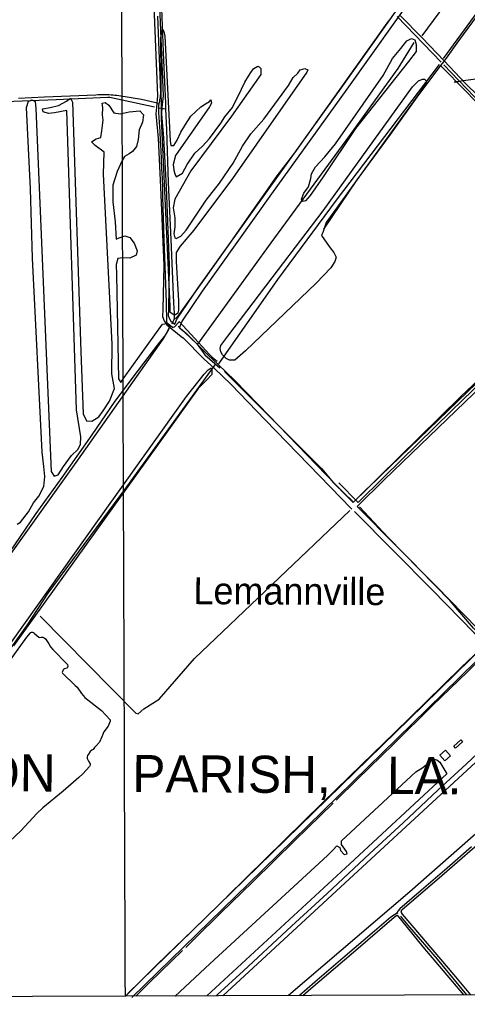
# Model space of a CAD drawing. Extents: x 3392644 to 3430565, y 576657 to 602123.
# Drawn here: x 3406749 to 3409164, y 582044 to 587349 of the extents above; entities that cross this region are included whole.
import ezdxf

# ---------------------------------------------------------------- set-up
doc = ezdxf.new("R2010")
doc.units = 0
for name, color, linetype in [('V-BLDG-OTLN', 7, 'Continuous'), ('V-DTCH-CNTR', 7, 'Continuous'), ('V-GRID-FRAM', 7, 'Continuous'), ('V-GRID-MAJR', 7, 'Continuous'), ('V-ROAD-CNTR', 7, 'Continuous'), ('V-SITE-VEGE', 7, 'Continuous'), ('V-TOPO-GNAM-IDEN', 7, 'Continuous'), ('V-TOPO-SHOR', 7, 'Continuous'), ('V-UTIL-LINE', 7, 'Continuous')]:
    doc.layers.add(name, color=color, linetype=linetype)

msp = doc.modelspace()

# ---------------------------------------------------------------- linework, layer by layer
at = {"layer": 'V-BLDG-OTLN'}
for points in [[(3409137.6, 583454.6), (3409100.6, 583421), (3409091.2, 583431.3), (3409128.2, 583464.9)], [(3409042.7, 583352.1), (3409072.2, 583379.1), (3409045.2, 583408.7), (3409015.7, 583381.7)]]:
    msp.add_lwpolyline(points, close=True, dxfattribs=at)
at = {"layer": 'V-DTCH-CNTR'}
for points in [[(3409647, 587959), (3409624.9, 587929.9), (3409540.6, 587814.5), (3409446.6, 587687.7), (3409353.5, 587558.7), (3409216, 587370.3), (3409116.2, 587234.7), (3409048.9, 587141.1), (3409039.4, 587126.6), (3409035.3, 587120.4), (3409019.6, 587101.1), (3409014.3, 587094.6), (3408890.9, 586930.1), (3408748, 586728.7), (3408567.8, 586484.8), (3408387.6, 586219.2)], [(3407492.4, 587367.2), (3407508.1, 586956.3), (3407507.8, 586948.1), (3407507.1, 586940), (3407506.3, 586931.8), (3407505.2, 586923.7), (3407503.8, 586915.6), (3407502.2, 586907.6), (3407500.4, 586899.7), (3407500, 586897.4), (3407499.3, 586893.7), (3407498.4, 586887.8), (3407497.7, 586881.8), (3407497.3, 586875.8), (3407497, 586869.7), (3407497, 586863.7), (3407497.2, 586857.7), (3407497.6, 586851.7), (3407498.2, 586845.7), (3407501.5, 586795.5), (3407504.6, 586745.4), (3407507.5, 586695.2), (3407510.1, 586645), (3407512.5, 586594.8), (3407514.7, 586544.6), (3407516.7, 586494.4), (3407518.5, 586444.2), (3407520.1, 586394), (3407527.2, 586164.2)], [(3409039.4, 587126.6), (3408919.7, 587250.4), (3408803.6, 587369)], [(3409928.4, 586167.2), (3409775.2, 586325.2), (3409562, 586545.6), (3409327.7, 586783.7), (3409156.4, 586961.6), (3409019.6, 587101.1)], [(3409039.4, 587126.6), (3409153.9, 587005.2), (3409288.2, 586873), (3409454.9, 586698.5), (3409643, 586502.2), (3409785.6, 586360.5), (3409964.8, 586171.9)], [(3407500, 586897.4), (3407405.1, 586917.7), (3407282.9, 586937.4), (3407272.8, 586938.9), (3407262.6, 586940.2), (3407252.3, 586941.3), (3407242.1, 586942.2), (3407231.8, 586943), (3407221.5, 586943.4), (3407211.2, 586943.7), (3407201, 586943.8), (3407190.7, 586943.6), (3407180.4, 586943.3), (3407170.1, 586942.7), (3407159.8, 586941.9), (3407020.9, 586935.8), (3406881.9, 586930), (3406742.9, 586924.3)], [(3407527.2, 586164.2), (3407539.5, 585825.5), (3407541.7, 585715.3), (3407545.1, 585713), (3407574.1, 585689.7), (3407576.4, 585689.6), (3407583.3, 585691.8), (3407608.8, 585719.6), (3407610, 585721.9), (3407713.3, 585608.4), (3407772.1, 585543.6), (3407788.8, 585526.3), (3407813.4, 585506.4)], [(3410023.7, 586158.2), (3410001, 586135), (3409981, 586115.2), (3409793.5, 585934.6), (3409482.4, 585632), (3409077.8, 585238.5), (3408713.3, 584882), (3408575.6, 584745.8), (3408572.1, 584747.2), (3408471.1, 584851.2)], [(3409182.8, 582089.4), (3409092.7, 582198.3), (3408907.2, 582416.2), (3408813.8, 582525.5), (3408808.5, 582534.5), (3408807.9, 582537.3), (3408807.3, 582543.5), (3408808.1, 582544.9), (3408809.5, 582548.3), (3409025.3, 582733.7), (3409286, 582959.6), (3409402.1, 583061.5), (3409500.5, 583147.9), (3409737.2, 583347.4), (3409967.1, 583549.1), (3410164.7, 583718.4), (3410319.6, 583853.5), (3410527.7, 584033), (3410699.4, 584182.2), (3410804.5, 584272.9)], [(3408276.7, 582086.1), (3408319.8, 582123.9), (3408549, 582320.8), (3408768.3, 582508.3), (3408782.9, 582519.7), (3408784.3, 582519), (3408923.9, 582348.8), (3409143.1, 582089.3)]]:
    msp.add_lwpolyline(points, dxfattribs=at)
at = {"layer": 'V-GRID-FRAM'}
msp.add_lwpolyline([(3396720.3, 600227.7), (3428325.7, 600342.6), (3428399.7, 582159.3), (3396778.5, 582044.3), (3396720.3, 600227.7)], dxfattribs=at)
at = {"layer": 'V-GRID-MAJR'}
msp.add_spline([(3407318.9, 582082.7), (3407297.7, 588140.7), (3407276.6, 594201.8), (3407255.4, 600262.9), (3407255.4, 600266)], degree=3, dxfattribs=at)
at = {"layer": 'V-ROAD-CNTR'}
for points in [[(3407363.9, 589730.8), (3407387.6, 589307.2), (3407422.5, 588520.5), (3407454.4, 587862.2), (3407492.5, 586938.6), (3407486.2, 586877), (3407483.2, 586840.9), (3407495.3, 586709.7), (3407509.1, 586445.7), (3407525.9, 586023.7), (3407521.7, 585787.5), (3407518.7, 585747.8), (3407528.4, 585724.8), (3407542.5, 585702.5), (3407629.7, 585633.1)], [(3407393.4, 589740.1), (3407417.6, 589308.7), (3407452.4, 588521.9), (3407484.4, 587863.5), (3407522.6, 586937.7), (3407516, 586874.2), (3407513.3, 586841), (3407525.2, 586711.9), (3407539.1, 586447), (3407555.9, 586024.1), (3407551.7, 585786.1), (3407549.2, 585752.7), (3407555.1, 585738.8), (3407565.1, 585722.8), (3407586.1, 585706.1)], [(3407586.1, 585706.1), (3407597.1, 585734.1), (3407711.2, 585901.9), (3408084.8, 586426.5), (3408491.3, 586992), (3408869.5, 587524.3), (3409161.2, 587932.8), (3409275.8, 588090.6), (3409321.6, 588159.8)], [(3407610.7, 585686.6), (3407623.8, 585720), (3407735.8, 585884.8), (3408109.2, 586409), (3408515.7, 586974.6), (3408894, 587506.9), (3409185.5, 587915.3), (3409300.4, 588073.5), (3409345.2, 588141.1)], [(3409939, 586099.5), (3409831.9, 585994.6), (3409369.7, 585539.7), (3408696.3, 584891.4), (3408548.3, 584744.8)], [(3409949.3, 586067.6), (3409852.9, 585973.2), (3409390.7, 585518.2), (3408717.3, 584869.9), (3408569.4, 584723.5)], [(3407610.7, 585686.6), (3407648.3, 585656.6)], [(3407649.7, 585655.4), (3407764.8, 585538.8), (3407818, 585491.6), (3407910.3, 585402.9), (3408095, 585212.5), (3408504.6, 584788.8), (3408548.3, 584744.8)], [(3407628.3, 585634.3), (3407744.2, 585517.1), (3407797.6, 585469.6), (3407889.1, 585381.6), (3408073.5, 585191.6), (3408483.2, 584767.8), (3408507.5, 584743.3)], [(3408508.9, 584741.9), (3408540.8, 584709.7)], [(3408554.2, 584696.2), (3408973.7, 584273.2), (3409199.9, 584041.6), (3409268.5, 583986.1)], [(3408569.4, 584723.5), (3408995.1, 584294.2), (3409220.1, 584063.8), (3409290, 584007.2)], [(3409268.5, 583986.1), (3408926.5, 583651.5), (3407961.3, 582711), (3407333, 582096.6)], [(3409301.6, 583976.6), (3408947.4, 583630), (3407982.3, 582689.5), (3407354, 582075.2)]]:
    msp.add_lwpolyline(points, dxfattribs=at)
at = {"layer": 'V-SITE-VEGE'}
for p, q in [((3407001.1, 586908.9), (3407022.2, 586924.6)), ((3407022.2, 586924.6), (3407033.7, 586903.6)), ((3406786.2, 586875.8), (3406795.6, 586908.3)), ((3406806.9, 586435.7), (3406786.2, 586875.8)), ((3406795.6, 586908.3), (3406816.4, 586915.7)), ((3406816.4, 586915.7), (3406832.5, 586906.9)), ((3406832.5, 586906.9), (3406835.2, 586869.9)), ((3406835.2, 586869.9), (3406919.2, 584912.5)), ((3406872.2, 586868.5), (3406913.5, 586875.2)), ((3406875.7, 586852), (3406872.2, 586868.5)), ((3406913.5, 586875.2), (3406959.1, 586885.8)), ((3406959.1, 586885.8), (3407001.1, 586908.9)), ((3407033.7, 586903.6), (3407078.7, 585559.5)), ((3407193.8, 586897.7), (3407210.3, 586901.2)), ((3407197, 586873), (3407193.8, 586897.7)), ((3407195.6, 586836.1), (3407197, 586873)), ((3407210.3, 586901.2), (3407230.4, 586888.2)), ((3407230.4, 586888.2), (3407257.6, 586846.1)), ((3406904.1, 586842.7), (3406875.7, 586852)), ((3406937.1, 586845.6), (3406904.1, 586842.7)), ((3407003.3, 586859.6), (3406937.1, 586845.6)), ((3407054.7, 585244.2), (3407003.3, 586859.6)), ((3407198.7, 586807.2), (3407195.6, 586836.1)), ((3407257.6, 586846.1), (3407290.3, 586840.8)), ((3407290.3, 586840.8), (3407340, 586851.3)), ((3407340, 586851.3), (3407397.7, 586857.4)), ((3407397.7, 586857.4), (3407417.5, 586836.1)), ((3407417.5, 586836.1), (3407411.9, 586795.3)), ((3407192.4, 586750), (3407198.7, 586807.2)), ((3407411.9, 586795.3), (3407394, 586754.9)), ((3407136.8, 586690.4), (3407162, 586705.9)), ((3407162, 586705.9), (3407187, 586713.2)), ((3407187, 586713.2), (3407192.4, 586750)), ((3407394, 586754.9), (3407387.9, 586701.7)), ((3407156.6, 586669.2), (3407136.8, 586690.4)), ((3407204.6, 586634.6), (3407156.6, 586669.2)), ((3407378.3, 586665.1), (3407356.8, 586637.2)), ((3407387.9, 586701.7), (3407378.3, 586665.1)), ((3407200.2, 586515.7), (3407204.6, 586634.6)), ((3407314.7, 586610), (3407301.6, 586589.9)), ((3407339.9, 586625.5), (3407314.7, 586610)), ((3407356.8, 586637.2), (3407339.9, 586625.5)), ((3407301.6, 586589.9), (3407274.7, 586529.3)), ((3407248.6, 585598.3), (3407200.2, 586515.7)), ((3407274.7, 586529.3), (3407251.5, 586456.3)), ((3407251.5, 586456.3), (3407252.2, 586366)), ((3406817.8, 586061.7), (3406806.9, 586435.7)), ((3407252.2, 586366), (3407264.7, 586258.7)), ((3407264.7, 586258.7), (3407269.5, 586164.1)), ((3407286.2, 586171.7), (3407315.3, 586183)), ((3407315.3, 586183), (3407343.8, 586173.7)), ((3407269.5, 586164.1), (3407286.2, 586171.7)), ((3407343.8, 586173.7), (3407367.3, 586144.1)), ((3407367.3, 586144.1), (3407382.2, 586102.5)), ((3407377.2, 586078.1), (3407343.8, 586062.9)), ((3407382.2, 586102.5), (3407377.2, 586078.1)), ((3406869.7, 585017), (3406817.8, 586061.7)), ((3407278, 586061.2), (3407268.6, 586028.7)), ((3407268.6, 586028.7), (3407270.6, 585971.1)), ((3407302.8, 586064.4), (3407278, 586061.2)), ((3407343.8, 586062.9), (3407302.8, 586064.4)), ((3407270.6, 585971.1), (3407282.8, 585412.3)), ((3407311.8, 585419.5), (3407519.7, 585707.4)), ((3407519.7, 585707.4), (3407544.5, 585710.6)), ((3407544.5, 585710.6), (3407556.2, 585693.7)), ((3407551.5, 585677.5), (3407520.8, 585625.3)), ((3407556.2, 585693.7), (3407551.5, 585677.5)), ((3407520.8, 585625.3), (3407061.2, 584973)), ((3407246.8, 585438.3), (3407248.6, 585598.3)), ((3407078.7, 585559.5), (3407090.9, 585222.3)), ((3407260.3, 585359.8), (3407246.8, 585438.3)), ((3407649.1, 585316.7), (3407743.9, 585436.4)), ((3407743.9, 585436.4), (3407765.4, 585460.2)), ((3407785, 585434.9), (3407759.3, 585407.1)), ((3407765.4, 585460.2), (3407782.2, 585471.9)), ((3407782.2, 585471.9), (3407785.9, 585459.5)), ((3407785.9, 585459.5), (3407785, 585434.9)), ((3407282.8, 585412.3), (3407294.4, 585391.4)), ((3407294.4, 585391.4), (3407311.8, 585419.5)), ((3407759.3, 585407.1), (3407712.3, 585359.5)), ((3407712.3, 585359.5), (3406716.1, 583971.7)), ((3407233.1, 585291), (3407260.3, 585359.8)), ((3407198.4, 585238.9), (3407233.1, 585291)), ((3407246.2, 584752.7), (3407649.1, 585316.7)), ((3407078.2, 585099.6), (3407054.7, 585244.2)), ((3407090.9, 585222.3), (3407110.1, 585184.7)), ((3407176.6, 585206.9), (3407198.4, 585238.9)), ((3407110.1, 585184.7), (3407138.8, 585183.6)), ((3407138.8, 585183.6), (3407176.6, 585206.9)), ((3407076.6, 585058.6), (3407078.2, 585099.6)), ((3406879.1, 584938.7), (3406869.7, 585017)), ((3407029.2, 584998.8), (3407063.3, 585030.4)), ((3407063.3, 585030.4), (3407076.6, 585058.6)), ((3407061.2, 584973), (3406567.3, 584285.1)), ((3406985.9, 584938.8), (3407029.2, 584998.8)), ((3406885.3, 584885.1), (3406879.1, 584938.7)), ((3406919.2, 584912.5), (3406934.7, 584887.3)), ((3406955.6, 584894.8), (3406985.9, 584938.8)), ((3406879.3, 584831.9), (3406885.3, 584885.1)), ((3406934.7, 584887.3), (3406955.6, 584894.8)), ((3406852.7, 584779.5), (3406879.3, 584831.9)), ((3406704.5, 583992.6), (3407246.2, 584752.7)), ((3406796.2, 584695.4), (3406822.6, 584743.7)), ((3406822.6, 584743.7), (3406852.7, 584779.5)), ((3406753, 584639.5), (3406796.2, 584695.4)), ((3406736.1, 584627.8), (3406753, 584639.5)), ((3407844.5, 582084.6), (3409233.2, 583365.6)), ((3408952.8, 583339), (3408978.3, 583362.7)), ((3408978.3, 583362.7), (3408998.7, 583357.9)), ((3408885.3, 583292.3), (3408923.1, 583315.5)), ((3408923.1, 583315.5), (3408952.8, 583339)), ((3408998.7, 583357.9), (3409014.6, 583345)), ((3409014.6, 583345), (3409053.4, 583282)), ((3408485.3, 582921.1), (3408885.3, 583292.3)), ((3409053.4, 583282), (3408530.1, 582796.3)), ((3409392.7, 583121.6), (3408853.2, 582644.8)), ((3408438.2, 582869.4), (3408459.7, 582893.3)), ((3408459.7, 582893.3), (3408475.8, 582884.5)), ((3408484.6, 582900.6), (3408485.3, 582921.1)), ((3408512, 582862.6), (3408484.6, 582900.6)), ((3407774.6, 582257.6), (3408408.5, 582841.8)), ((3408408.5, 582841.8), (3408438.2, 582869.4)), ((3408475.8, 582884.5), (3408479.3, 582867.9)), ((3408479.3, 582867.9), (3408499, 582846.7)), ((3408499, 582846.7), (3408515.6, 582850.2)), ((3408515.6, 582850.2), (3408512, 582862.6)), ((3408530.1, 582796.3), (3407758.9, 582084.3)), ((3408853.2, 582644.8), (3408199.1, 582085.9)), ((3407587.2, 582083.6), (3407774.6, 582257.6)), ((3407758.9, 582084.3), (3407587.2, 582083.6)), ((3408199.1, 582085.9), (3407844.5, 582084.6))]:
    msp.add_line(p, q, dxfattribs=at)
for points in [[(3407593.6, 586043.8), (3407606, 585832.1), (3407606, 585782.3), (3407601.9, 585765.6), (3407589.4, 585757.3), (3407581.1, 585757.3), (3407560.4, 585769.8), (3407560.4, 585803), (3407514.7, 586815.9), (3407510.6, 587251.8), (3407518.9, 587297.5), (3407527.2, 587285), (3407531.3, 587260.1), (3407560.4, 586695.5), (3407564.5, 586670.6), (3407581.1, 586670.6), (3407597.7, 586699.7), (3407618.4, 586741.2), (3407643.3, 586782.7), (3407672.4, 586828.4), (3407726.3, 586878.2), (3407751.2, 586894.8), (3407771.9, 586907.3), (3407780.2, 586915.6), (3407784.4, 586899), (3407771.9, 586878.2), (3407589.4, 586616.7), (3407577, 586566.9), (3407581.1, 586537.8), (3407585.3, 586517), (3407593.6, 586500.4), (3407626.7, 586521.2), (3407651.6, 586566.9), (3407693.1, 586629.1), (3407734.6, 586666.5), (3407771.9, 586708), (3407834.1, 586791), (3407854.9, 586824.2), (3407896.4, 586874.1), (3407946.1, 586973.7), (3407962.7, 587011), (3407983.5, 587044.3), (3408000.1, 587069.2), (3408012.5, 587085.8), (3408033.3, 587098.2), (3408041.6, 587094.1), (3408049.9, 587085.8), (3408049.9, 587052.6), (3407892.2, 586828.4), (3407672.4, 586533.6), (3407585.3, 586380), (3407577, 586334.4), (3407585.3, 586280.4), (3407585.3, 586230.6), (3407581.1, 586193.2), (3407585.3, 586172.5), (3407593.6, 586168.3), (3407618.4, 586180.8), (3407647.5, 586214), (3407755.3, 586375.9), (3407825.9, 586467.2), (3407900.5, 586575.2), (3407950.3, 586666.5), (3407995.9, 586732.9), (3408066.4, 586811.8), (3408145.3, 586919.7), (3408199.2, 586994.4), (3408224.1, 587036), (3408249, 587060.9), (3408261.4, 587077.5), (3408286.3, 587085.8), (3408302.9, 587077.5), (3408298.7, 587065), (3407896.4, 586492.1), (3407689, 586214), (3407614.3, 586126.8), (3407593.6, 586093.6)], [(3408560.1, 586762), (3408385.9, 586500.4), (3408315.3, 586400.8), (3408290.4, 586371.7), (3408278, 586367.6), (3408269.7, 586380), (3408282.2, 586413.3), (3408307, 586446.5), (3408319.5, 586492.1), (3408323.6, 586517), (3408344.4, 586554.4), (3408394.2, 586608.4), (3408452.2, 586678.9), (3408709.4, 587048.4), (3408759.2, 587139.7), (3408804.8, 587193.7), (3408838, 587235.2), (3408862.9, 587247.7), (3408879.5, 587239.4), (3408887.8, 587214.5), (3408887.8, 587177.1), (3408846.3, 587123.1)], [(3408145.3, 586002.3), (3408385.9, 586317.8), (3408867, 586986.1), (3408900.2, 587019.4), (3408921, 587027.7), (3408933.4, 587027.7), (3408941.7, 587019.4), (3408941.7, 587002.7), (3408800.7, 586807.6), (3408402.4, 586255.5), (3408385.9, 586205.7), (3408377.6, 586184.9), (3408406.6, 586143.4), (3408423.2, 586118.5), (3408443.9, 586093.6), (3408456.4, 586068.7), (3408448.1, 586043.8), (3408427.3, 586010.6), (3408348.5, 585927.5), (3407966.9, 585562.2), (3407908.8, 585512.4), (3407879.8, 585512.4), (3407863.2, 585520.7), (3407842.4, 585541.5), (3407834.1, 585558.1), (3407830, 585574.7), (3407834.1, 585591.3), (3407871.5, 585641.1)]]:
    msp.add_lwpolyline(points, close=True, dxfattribs=at)
at = {"layer": 'V-TOPO-SHOR'}
for p, q in [((3408919.9, 587261.6), (3409456.6, 587991.4)), ((3409035.7, 587139.6), (3409612.3, 587930.8)), ((3408785.1, 587365.1), (3409022, 587119.5)), ((3407501.6, 586873), (3407536.3, 586867.9)), ((3408788.2, 582529), (3408785.3, 582532.9))]:
    msp.add_line(p, q, dxfattribs=at)
for points in [[(3407464.2, 588446.3), (3407466.2, 588409.9), (3407478.1, 588196.5), (3407490.7, 587925.7), (3407491.1, 587917.4), (3407502.7, 587678.6), (3407513, 587408.8), (3407525.4, 587127.6), (3407535.2, 586898.2), (3407536.3, 586867.9), (3407540.5, 586754.7), (3407550.5, 586470.9), (3407565.1, 586162.9)], [(3408738.8, 587341.8), (3408541.8, 587067.1), (3408231, 586630.9), (3408130.4, 586498.9), (3408099.2, 586454.3), (3407959.5, 586255), (3407885.8, 586149.5)], [(3407709.8, 585598.2), (3408105.3, 586144.7), (3408529.4, 586724), (3408668, 586917.1), (3408790.4, 587085.6), (3408875.9, 587225.2)], [(3409011.6, 587106.9), (3408456.9, 586375.5), (3408138.8, 585948.1), (3407820.9, 585492.1)], [(3409036.2, 587104.6), (3409323.3, 586806.8), (3409588.6, 586539.2), (3409972.5, 586141.7)], [(3406624.4, 586906.3), (3406945.4, 586918.2), (3407221.8, 586931.5), (3407235.6, 586929.9), (3407476, 586878.5)], [(3407565.1, 586162.9), (3407579.4, 585821.2), (3407583, 585764), (3407582.6, 585744.1), (3407579.6, 585729.7), (3407571.6, 585712.7), (3407569.5, 585707.2)], [(3407885.8, 586149.5), (3407739.8, 585944), (3407600.1, 585748.7), (3407579.6, 585729.7)], [(3407556, 585687.5), (3407535.2, 585649.4), (3407498.5, 585602), (3407388.8, 585459), (3407262.2, 585291), (3407138, 585109.1), (3406977, 584879.8), (3406836.7, 584685.2), (3406694.1, 584477.6), (3406534.8, 584261.3), (3406427.1, 584115.6), (3406406.7, 584093.3), (3406403.8, 584087.2), (3406403.7, 584081), (3406406.3, 584074), (3406413, 584063.6), (3406476.1, 583990), (3406593.5, 583874), (3406611.7, 583856.5), (3406619.8, 583846.7), (3406623.8, 583843.1), (3406651.8, 583830.8), (3406657.9, 583828.7)], [(3407602.9, 585696.2), (3407705.7, 585598.2), (3407746.9, 585541), (3407829.1, 585471.6)], [(3407800.7, 585486.7), (3407528.4, 585109.8), (3407325, 584828.7), (3406901.6, 584256.7), (3406790.1, 584084.8), (3406691.7, 583949.2), (3406626.1, 583853.4)], [(3407853.8, 585451.2), (3408376.1, 584928.6), (3408442, 584851)], [(3408573.4, 584769.5), (3409128.7, 585316.6), (3409259.4, 585440)], [(3408545.4, 584750.7), (3408452.7, 584839.4), (3408442, 584851)], [(3406859.2, 584131.2), (3407375.6, 583608.8), (3407388.8, 583605.5), (3407418.3, 583632), (3407500.6, 583685.1), (3407691.1, 583903.4), (3408529.1, 584701.2)], [(3409260.4, 584008), (3409197.5, 584067.2), (3409071.7, 584215.1), (3408737.4, 584556.9), (3408581.8, 584721.2)], [(3406699.9, 583895.9), (3406788.3, 584019.1), (3406806.6, 584042.7), (3406808, 584044.1), (3406813.5, 584045.3), (3406817.7, 584045.2), (3406823.8, 584043.1), (3406827.2, 584040.2), (3406842, 584027.6), (3406851.4, 584018.4), (3406858.3, 584016.2), (3406865.2, 584018.2), (3406873.4, 584018.7), (3406880.9, 584015.8), (3406887.7, 584010.1), (3406895.7, 583999.7), (3406905.6, 583982.3), (3406914.9, 583966.3), (3406927.7, 583952.3), (3407004.3, 583873.8), (3407007, 583871.7), (3407008.8, 583860), (3407004.6, 583851.8), (3406997, 583850.6), (3406988.7, 583847.4), (3406983.8, 583842.7), (3406978, 583829), (3406980, 583824.2), (3407047.9, 583757.5), (3407059.4, 583748.4), (3407082.1, 583715), (3407100.2, 583694), (3407190.7, 583622.7), (3407236.4, 583572.4), (3407237.6, 583565.5), (3407225.4, 583538.9), (3407203.5, 583508.5), (3407191.2, 583480.6), (3407179.7, 583453.4), (3407159.3, 583431.8), (3407152.3, 583423), (3407145.2, 583413.5), (3407138.9, 583409.6), (3407129.9, 583402.2), (3407120, 583388.7), (3407115, 583380.5), (3407112.1, 583373), (3407113.3, 583364.8), (3407120.5, 583349.5), (3407128.5, 583335.6), (3407128.3, 583328.7), (3407125.4, 583321.9), (3407088.9, 583281.5), (3407067.2, 583262.7)], [(3409261.2, 583980.1), (3409132.1, 583857.6), (3408941.4, 583669.3), (3408771.1, 583503.2), (3408593.8, 583332.4), (3408383.6, 583128.1), (3408176.9, 582923.7), (3407971.6, 582722.1), (3407866.2, 582618.2)], [(3409301, 583966.6), (3409164.1, 583832.5), (3408976.5, 583649.9), (3408765.8, 583442.3), (3408569.8, 583251.6), (3408456, 583139.7)], [(3409711.5, 583850.7), (3409628.9, 583774.1), (3409533.7, 583685.4), (3409431.4, 583590), (3409313.2, 583481.9), (3409157, 583334.7), (3409005.8, 583196.4), (3408816.7, 583017.7), (3408638.2, 582853.1), (3408407.1, 582637.4), (3408215.9, 582460.1), (3407956.9, 582220.3), (3407814.1, 582089.4), (3407808.9, 582084.4)], [(3407067.2, 583262.7), (3406984, 583188.2), (3406874.3, 583098.5), (3406842.1, 583068.2), (3406755.7, 582975.2), (3406665.3, 582890.6)], [(3408439.1, 583122.8), (3408235.5, 582924), (3408005.8, 582700.3), (3407834.4, 582533.1), (3407693.9, 582394.3), (3407644.7, 582345.7)], [(3409186.4, 582887.6), (3409055.1, 582773.8), (3408915.6, 582654.6), (3408799.7, 582554.2), (3408789.1, 582541.4), (3408785.5, 582533.2), (3408785.3, 582532.9), (3408782.7, 582529.8), (3408771.6, 582521.8), (3408750.8, 582509.2), (3408662.1, 582433.6), (3408491.8, 582287), (3408341.7, 582157.8), (3408259.1, 582086.1)], [(3407827.1, 582578.7), (3407684.7, 582441.4), (3407490.6, 582253.1), (3407319.8, 582082.7)], [(3409160.7, 582089.3), (3409001.8, 582281.8), (3408854.1, 582454.8), (3408809.1, 582508.6), (3408804.4, 582513.6)], [(3407627.8, 582328.9), (3407449.5, 582156.4), (3407375.5, 582082.9)]]:
    msp.add_lwpolyline(points, dxfattribs=at)
at = {"layer": 'V-UTIL-LINE'}
for points in [[(3410988.1, 588365.6), (3410864.6, 588211.6), (3410732.5, 588047.8), (3410537.6, 587814.7), (3410153.4, 587346.1), (3409973, 587120.7), (3409436.1, 587059.3), (3409093.1, 587011.9)], [(3409093.1, 587011.9), (3409126.8, 587016.5)]]:
    msp.add_lwpolyline(points, dxfattribs=at)

# ---------------------------------------------------------------- texts
at = {"layer": 'V-TOPO-GNAM-IDEN'}
for s, height, p in [('Lemannville', 145, (3407686.1, 584196.9)), ('ASCENSION', 200, (3405366.8, 583194.8)), ('PARISH,', 200, (3407356.2, 583183.5)), ('LA.', 200, (3408729.9, 583173.8))]:
    msp.add_text(s, height=height, rotation=359.6858, dxfattribs=at).set_placement(p)

doc.saveas('drawing.dxf')
